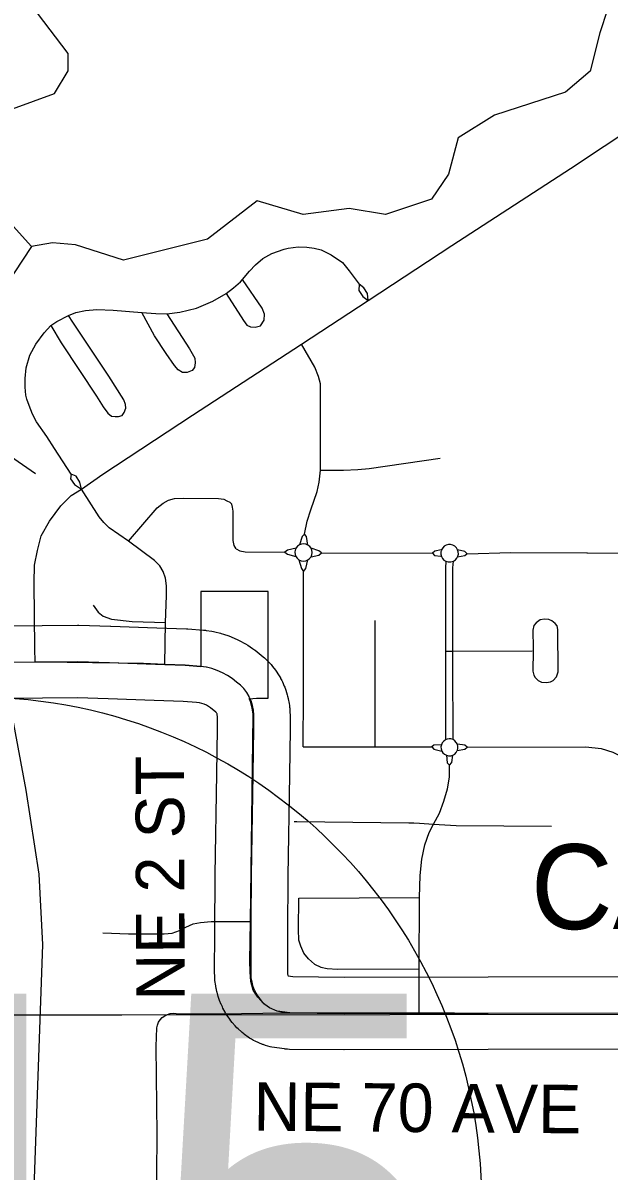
# Model space of a CAD drawing. Extents: x -1403959 to 81668, y -1400582 to 11018.
# Drawn here: x 7193.8 to 7240.5, y 8904.3 to 8995.9 of the extents above; entities that cross this region are included whole.
import ezdxf

# ---------------------------------------------------------------- set-up
doc = ezdxf.new("R2010")
doc.units = 0
for name, color, linetype in [('tdCiCityDivCarto', 7, 'Continuous'), ('tdCiCoBndryTxt', 7, 'Continuous'), ('tdCiRRCL', 7, 'Continuous'), ('tdCiSectLine', 7, 'Continuous'), ('tdCiSectTwpRng', 7, 'Continuous'), ('tdCiUABTitleFrame', 7, 'Continuous'), ('tdCoCityStreetMajor', 7, 'Continuous'), ('tdCoClipBndry', 7, 'Continuous'), ('tdCoDivCarto', 7, 'Continuous'), ('tdCoSectNmbr', 7, 'Continuous'), ('tdCoStrucSecCoName', 7, 'Continuous'), ('tdCoSurfAsphalt', 7, 'Continuous'), ('tdCoSurfBitum', 7, 'Continuous'), ('tdCoSurfEarth', 7, 'Continuous'), ('tdCoTwpNameTxt', 7, 'Continuous')]:
    doc.layers.add(name, color=color, linetype=linetype)

msp = doc.modelspace()

# ---------------------------------------------------------------- linework, layer by layer
at = {"layer": 'tdCiCityDivCarto'}
msp.add_lwpolyline([(7204.662, 8895.454), (7204.534, 8895.98), (7204.469, 8896.616), (7204.417, 8898.277), (7204.456, 8900.703), (7204.43, 8903.623), (7204.434, 8904.02), (7204.461, 8907.198), (7204.397, 8914.226), (7204.429, 8915.705), (7204.487, 8915.937), (7204.583, 8916.155), (7204.715, 8916.354), (7204.88, 8916.527), (7205.071, 8916.67), (7205.284, 8916.778), (7205.512, 8916.847), (7205.749, 8916.877), (7205.987, 8916.866), (7209.502, 8916.835), (7214.602, 8916.899), (7215.067, 8916.898)], dxfattribs=at)
at = {"layer": 'tdCiCoBndryTxt'}
for points in [[(7190.264, 8944.892), (7192.488, 8944.899), (7194.719, 8944.916), (7198.135, 8944.942), (7200.657, 8944.875), (7204.341, 8944.743), (7205.09, 8944.716), (7206.698, 8944.66), (7207.943, 8944.56)], [(7211.852, 8942.059), (7211.81, 8942.152), (7211.614, 8942.481), (7211.38, 8942.785), (7211.112, 8943.059), (7210.814, 8943.299), (7210.459, 8943.585), (7210.081, 8943.838), (7209.683, 8944.057), (7209.266, 8944.24), (7208.835, 8944.386), (7208.411, 8944.488), (7208.393, 8944.493), (7207.943, 8944.56)], [(7211.887, 8941.98), (7211.852, 8942.059)], [(7211.981, 8924.194), (7212.008, 8927.865), (7212.141, 8935.964), (7212.191, 8939.565), (7212.174, 8940.677), (7212.15, 8941.059), (7212.08, 8941.436), (7211.967, 8941.802), (7211.887, 8941.98)], [(7215.067, 8916.898), (7214.047, 8917.053), (7213.447, 8917.315), (7213.156, 8917.53), (7212.89, 8917.775), (7212.652, 8918.048), (7212.446, 8918.346), (7212.274, 8918.664), (7212.138, 8918.999), (7212.039, 8919.347), (7211.979, 8919.704), (7211.959, 8920.066), (7211.975, 8923.368), (7211.981, 8924.194)], [(7215.067, 8916.898), (7219.393, 8916.866), (7225.382, 8916.875), (7230.891, 8916.882), (7241.8, 8916.914), (7244.726, 8916.898), (7251.584, 8916.861)]]:
    msp.add_lwpolyline(points, dxfattribs=at)
at = {"layer": 'tdCiRRCL'}
msp.add_lwpolyline([(7251.584, 8916.859), (7228.211, 8916.885), (7225.36, 8916.875), (7214.602, 8916.899), (7214.047, 8917.053), (7213.447, 8917.315), (7212.985, 8917.623), (7212.508, 8918.162), (7212.123, 8918.732), (7211.938, 8919.425), (7211.892, 8920.149), (7211.877, 8921.058), (7211.924, 8924.194), (7212.141, 8940.627), (7212.122, 8940.771), (7212.064, 8941.213), (7211.925, 8941.767), (7211.823, 8941.973), (7212.394, 8942.036), (7213.334, 8942.036), (7213.334, 8950.54), (7207.952, 8950.54), (7207.952, 8944.678), (7207.943, 8944.56), (7206.698, 8944.66), (7205.043, 8944.718), (7203.388, 8944.777), (7197.286, 8944.864), (7192.488, 8944.899)], dxfattribs=at)
at = {"layer": 'tdCiSectLine'}
for points in [[(7192.472, 8947.801), (7198.113, 8947.844), (7198.135, 8947.844), (7198.211, 8947.843), (7200.734, 8947.776), (7200.762, 8947.775), (7204.445, 8947.643), (7206.8, 8947.56), (7206.888, 8947.555), (7206.929, 8947.552), (7208.174, 8947.453), (7208.321, 8947.437), (7208.374, 8947.43), (7208.824, 8947.362), (7208.959, 8947.339), (7209.075, 8947.313), (7209.517, 8947.206), (7209.586, 8947.189), (7209.763, 8947.135), (7210.194, 8946.989), (7210.199, 8946.988), (7210.377, 8946.921), (7210.433, 8946.897), (7210.85, 8946.714), (7210.966, 8946.66), (7211.079, 8946.601), (7211.478, 8946.381), (7211.532, 8946.351), (7211.694, 8946.251), (7211.697, 8946.248), (7212.075, 8945.995), (7212.226, 8945.887), (7212.28, 8945.844), (7212.933, 8945.318), (7213.025, 8945.24), (7213.164, 8945.111), (7213.186, 8945.089), (7213.454, 8944.815), (7213.562, 8944.698), (7213.679, 8944.556), (7213.913, 8944.252), (7213.916, 8944.248), (7214.027, 8944.093), (7214.106, 8943.968), (7214.302, 8943.639), (7214.323, 8943.603), (7214.413, 8943.436), (7214.461, 8943.334), (7214.617, 8942.984), (7214.647, 8942.913), (7214.714, 8942.735), (7214.738, 8942.663), (7214.851, 8942.297), (7214.883, 8942.187), (7214.926, 8942.002), (7214.934, 8941.963), (7215.003, 8941.587), (7215.027, 8941.438), (7215.045, 8941.249), (7215.046, 8941.246), (7215.07, 8940.863), (7215.076, 8940.72), (7215.093, 8939.608), (7215.093, 8939.565), (7215.093, 8939.525), (7215.043, 8935.924), (7215.043, 8935.916), (7214.91, 8927.831), (7214.877, 8923.35), (7214.861, 8920.141), (7214.867, 8920.028), (7214.874, 8919.986), (7214.886, 8919.944), (7214.902, 8919.905), (7214.923, 8919.867), (7214.932, 8919.854), (7215.296, 8919.799), (7219.402, 8919.768), (7230.884, 8919.784), (7241.791, 8919.816)], [(7241.796, 8914.012), (7230.899, 8913.98), (7230.895, 8913.98), (7219.397, 8913.964), (7219.393, 8913.964), (7219.372, 8913.965), (7215.045, 8913.997), (7214.877, 8914.003), (7214.688, 8914.021), (7214.631, 8914.029), (7213.612, 8914.184), (7213.481, 8914.207), (7213.296, 8914.25), (7213.115, 8914.305), (7212.937, 8914.372), (7212.887, 8914.393), (7212.287, 8914.655), (7212.164, 8914.712), (7211.996, 8914.802), (7211.835, 8914.902), (7211.724, 8914.98), (7211.433, 8915.195), (7211.389, 8915.227), (7211.242, 8915.348), (7211.188, 8915.397), (7210.922, 8915.643), (7210.838, 8915.723), (7210.708, 8915.862), (7210.7, 8915.871), (7210.462, 8916.145), (7210.35, 8916.282), (7210.267, 8916.396), (7210.061, 8916.693), (7210.034, 8916.734), (7209.933, 8916.895), (7209.894, 8916.965), (7209.722, 8917.283), (7209.672, 8917.381), (7209.593, 8917.554), (7209.586, 8917.571), (7209.45, 8917.906), (7209.39, 8918.066), (7209.346, 8918.208), (7209.247, 8918.556), (7209.236, 8918.596), (7209.193, 8918.781), (7209.177, 8918.866), (7209.117, 8919.223), (7209.102, 8919.326), (7209.084, 8919.515), (7209.082, 8919.54), (7209.062, 8919.901), (7209.057, 8920.066), (7209.057, 8920.08), (7209.073, 8923.383), (7209.074, 8923.389), (7209.107, 8927.887), (7209.107, 8927.913), (7209.24, 8936.008), (7209.289, 8939.563), (7209.274, 8940.562), (7209.265, 8940.701), (7209.258, 8940.74), (7209.246, 8940.777), (7209.23, 8940.813), (7209.21, 8940.847), (7209.186, 8940.878), (7209.158, 8940.906), (7208.738, 8941.245), (7208.572, 8941.356), (7208.398, 8941.452), (7208.216, 8941.532), (7208.028, 8941.595), (7207.835, 8941.642), (7207.611, 8941.676), (7206.531, 8941.762), (7204.239, 8941.843), (7204.237, 8941.843), (7200.567, 8941.975), (7198.108, 8942.04), (7192.51, 8941.998)]]:
    msp.add_lwpolyline(points, dxfattribs=at)
at = {"layer": 'tdCiSectTwpRng'}
for points in [[(7238.912, 8985.249), (7251.647, 8993.648), (7255.058, 8995.875)], [(7194.689, 8952.648), (7194.689, 8952.65), (7194.905, 8953.807), (7195.219, 8954.983), (7195.866, 8956.16), (7196.787, 8957.375), (7197.611, 8958.199), (7198.415, 8958.713), (7200.12, 8959.904), (7207.277, 8964.61), (7215.983, 8970.278), (7221.313, 8973.767), (7228.001, 8978.139), (7238, 8984.648), (7238.912, 8985.249)], [(7197.592, 8959.91), (7196.282, 8961.949), (7195.647, 8962.91), (7194.843, 8964.082), (7194.517, 8964.69), (7194.24, 8965.391), (7194.072, 8965.896), (7193.996, 8966.205), (7193.925, 8966.835), (7193.925, 8967.546), (7194.023, 8968.399), (7194.311, 8969.398), (7194.772, 8970.266), (7195.435, 8971.189), (7195.982, 8971.762), (7196.461, 8972.096), (7197.391, 8972.556), (7197.981, 8972.791), (7198.747, 8972.965), (7199.648, 8973.041), (7200.956, 8972.992), (7203.249, 8972.793), (7204.355, 8972.731), (7205.244, 8972.706), (7206.277, 8972.824), (7207.597, 8973.16), (7208.9, 8973.698), (7209.964, 8974.319), (7210.556, 8974.762), (7211.126, 8975.251), (7211.286, 8975.443), (7211.837, 8976.092), (7212.331, 8976.619), (7212.912, 8977.118), (7213.629, 8977.498), (7214.606, 8977.862), (7214.915, 8977.949), (7215.735, 8978.036), (7216.414, 8978.025), (7217, 8977.938), (7217.549, 8977.792), (7218.358, 8977.401), (7219.275, 8976.787), (7219.807, 8976.136), (7220.586, 8975.073)], [(7209.964, 8974.319), (7211.351, 8972.157), (7211.613, 8971.799), (7211.923, 8971.656), (7212.281, 8971.632), (7212.71, 8971.751), (7213.021, 8972.181), (7213.044, 8972.658), (7212.854, 8973.135), (7211.286, 8975.443)], [(7220.586, 8975.073), (7220.57, 8974.563), (7220.893, 8974.077), (7221.313, 8973.767)], [(7221.313, 8973.767), (7221.265, 8974.31), (7220.969, 8974.783), (7220.586, 8975.073)], [(7205.244, 8972.706), (7207.057, 8969.915), (7207.463, 8969.151), (7207.51, 8968.794), (7207.439, 8968.412), (7207.272, 8968.173), (7206.866, 8968.006), (7206.485, 8968.006), (7206.151, 8968.221), (7205.864, 8968.579), (7205.197, 8969.533), (7204.266, 8970.94), (7203.249, 8972.793)], [(7195.982, 8971.762), (7196.8, 8970.392), (7198.255, 8968.173), (7199.615, 8966.122), (7200.163, 8965.263), (7200.521, 8964.762), (7200.831, 8964.524), (7201.118, 8964.5), (7201.38, 8964.5), (7201.666, 8964.595), (7201.833, 8964.81), (7201.976, 8965.168), (7201.952, 8965.454), (7201.809, 8965.836), (7200.617, 8967.72), (7197.73, 8972.038), (7197.391, 8972.556)], [(7216.237, 8955.106), (7216.434, 8956.14), (7216.723, 8957.047), (7217.244, 8958.514), (7217.399, 8959.266), (7217.495, 8960.231), (7217.515, 8965.75), (7217.495, 8967.12), (7217.36, 8967.699), (7217.051, 8968.452), (7215.983, 8970.278)], [(7217.495, 8960.231), (7219.333, 8960.207), (7220.496, 8960.283), (7221.391, 8960.35), (7227.066, 8961.165)], [(7197.592, 8959.91), (7197.562, 8959.523), (7197.877, 8959.063), (7198.415, 8958.713)], [(7198.415, 8958.713), (7198.3, 8959.262), (7198.01, 8959.729), (7197.592, 8959.91)], [(7205.09, 8944.716), (7205.127, 8948.052), (7205.207, 8950.216), (7205.215, 8950.986), (7205.127, 8951.596), (7204.946, 8952.126), (7204.684, 8952.576), (7204.263, 8952.998), (7202.179, 8954.552), (7200.632, 8955.627), (7200.218, 8956.048), (7199.84, 8956.484), (7198.415, 8958.713)], [(7202.179, 8954.552), (7204.47, 8957.204), (7204.941, 8957.595), (7205.382, 8957.82), (7205.842, 8957.948), (7206.596, 8957.987), (7209.376, 8957.948), (7209.786, 8957.905), (7210.04, 8957.785), (7210.263, 8957.654)], [(7210.782, 8953.945), (7210.623, 8954.212), (7210.531, 8954.601), (7210.536, 8956.956), (7210.494, 8957.273), (7210.426, 8957.499), (7210.263, 8957.654)], [(7216.237, 8955.106), (7216.045, 8954.918), (7215.824, 8954.25)], [(7216.503, 8954.238), (7216.392, 8954.914), (7216.237, 8955.106)], [(7210.782, 8953.945), (7211.062, 8953.777), (7211.488, 8953.69), (7214.651, 8953.667)], [(7215.562, 8954.006), (7214.869, 8953.826), (7214.651, 8953.667)], [(7214.651, 8953.667), (7214.861, 8953.504), (7215.545, 8953.329)], [(7215.564, 8953.997), (7215.496, 8953.846), (7215.467, 8953.671), (7215.484, 8953.495), (7215.545, 8953.329)], [(7215.569, 8954.008), (7215.562, 8954.006)], [(7216.749, 8953.987), (7216.643, 8954.129), (7216.503, 8954.238), (7216.34, 8954.308), (7216.165, 8954.334), (7215.989, 8954.314), (7215.824, 8954.25), (7215.681, 8954.145), (7215.569, 8954.008)], [(7217.593, 8953.634), (7217.379, 8953.793), (7216.749, 8953.987)], [(7216.749, 8953.308), (7216.816, 8953.472), (7216.839, 8953.647), (7216.817, 8953.823), (7216.749, 8953.987)], [(7216.749, 8953.308), (7217.383, 8953.445), (7217.593, 8953.634)], [(7217.593, 8953.634), (7226.435, 8953.589)], [(7227.147, 8953.858), (7226.628, 8953.756), (7226.435, 8953.589)], [(7226.435, 8953.589), (7226.615, 8953.404), (7227.11, 8953.343)], [(7227.156, 8953.814), (7227.12, 8953.691), (7227.115, 8953.511), (7227.156, 8953.337), (7227.239, 8953.178), (7227.36, 8953.046), (7227.51, 8952.948)], [(7227.17, 8953.863), (7227.147, 8953.858)], [(7228.453, 8953.871), (7228.359, 8954.024), (7228.229, 8954.147), (7228.072, 8954.234), (7227.898, 8954.278), (7227.719, 8954.277), (7227.546, 8954.231), (7227.391, 8954.142), (7227.262, 8954.016), (7227.17, 8953.863)], [(7228.125, 8952.953), (7228.274, 8953.052), (7228.394, 8953.186), (7228.454, 8953.305), (7228.475, 8953.346), (7228.513, 8953.521), (7228.505, 8953.7), (7228.453, 8953.871)], [(7229.185, 8953.574), (7229.025, 8953.727), (7228.453, 8953.871)], [(7228.454, 8953.305), (7229.025, 8953.409), (7229.202, 8953.553)], [(7229.202, 8953.553), (7229.205, 8953.555)], [(7229.205, 8953.555), (7232.708, 8953.642), (7238.777, 8953.623), (7238.811, 8953.623)], [(7238.811, 8953.623), (7241.557, 8953.585), (7244.506, 8953.642)], [(7194.719, 8944.916), (7194.709, 8945.984), (7194.65, 8951.238), (7194.689, 8952.648)], [(7215.545, 8953.329), (7215.647, 8953.184), (7215.783, 8953.07), (7215.967, 8952.982), (7216.133, 8952.957), (7216.331, 8952.982), (7216.503, 8953.057), (7216.642, 8953.166), (7216.749, 8953.308)], [(7215.783, 8953.07), (7215.986, 8952.366), (7216.153, 8952.132)], [(7216.153, 8952.132), (7216.329, 8952.366), (7216.503, 8953.057)], [(7227.11, 8953.343), (7227.156, 8953.337)], [(7227.51, 8952.948), (7227.49, 8952.4), (7227.49, 8945.787), (7227.49, 8944.776), (7227.49, 8939.288), (7227.483, 8938.696)], [(7227.51, 8952.948), (7227.711, 8952.898), (7227.908, 8952.894), (7228.125, 8952.953)], [(7228.086, 8938.713), (7228.081, 8944.787), (7228.081, 8945.787), (7228.081, 8952.422), (7228.125, 8952.953)], [(7216.131, 8938.138), (7216.142, 8942.333), (7216.153, 8948.73), (7216.153, 8952.132)], [(7199.354, 8949.446), (7199.768, 8948.887), (7200.167, 8948.56), (7200.814, 8948.328), (7202.462, 8948.154), (7205.127, 8948.052)], [(7221.871, 8948.167), (7221.871, 8948.226)], [(7221.871, 8938.149), (7221.871, 8948.167)], [(7234.475, 8945.801), (7234.461, 8944.178), (7234.544, 8943.859), (7234.655, 8943.664), (7234.877, 8943.428), (7235.155, 8943.29), (7235.557, 8943.262), (7235.862, 8943.317), (7236.07, 8943.442), (7236.334, 8943.72), (7236.487, 8944.122), (7236.445, 8947.507), (7236.39, 8947.799), (7236.251, 8947.979), (7235.973, 8948.201), (7235.724, 8948.298), (7235.377, 8948.326), (7235.03, 8948.27), (7234.725, 8948.048), (7234.544, 8947.812), (7234.461, 8947.452), (7234.473, 8946.005), (7234.475, 8945.801)], [(7227.49, 8945.787), (7228.081, 8945.787), (7234.403, 8945.801)], [(7228.433, 8938.344), (7228.35, 8938.496), (7228.232, 8938.621), (7228.086, 8938.713), (7227.906, 8938.772), (7227.78, 8938.78), (7227.625, 8938.755), (7227.483, 8938.696), (7227.342, 8938.597), (7227.231, 8938.464), (7227.157, 8938.309)], [(7216.131, 8938.138), (7221.871, 8938.149), (7226.404, 8938.131)], [(7227.157, 8938.309), (7226.554, 8938.278), (7226.404, 8938.131)], [(7226.404, 8938.131), (7226.563, 8937.956), (7227.191, 8937.803)], [(7227.157, 8938.309), (7227.125, 8938.139), (7227.136, 8937.967), (7227.191, 8937.803)], [(7228.427, 8937.838), (7229.04, 8937.943), (7229.217, 8938.121)], [(7229.217, 8938.121), (7229.04, 8938.274), (7228.433, 8938.344)], [(7228.437, 8937.874), (7228.472, 8938.004), (7228.474, 8938.177), (7228.433, 8938.344)], [(7229.217, 8938.121), (7238.685, 8938.127), (7239.912, 8938.012), (7240.85, 8937.703), (7241.8, 8937.241), (7242.481, 8936.714), (7243.226, 8935.879), (7244.048, 8936.521), (7244.717, 8936.971), (7245.192, 8937.228), (7245.719, 8937.421), (7246.816, 8937.728), (7247.561, 8937.784), (7264.117, 8937.835)], [(7227.191, 8937.803), (7227.285, 8937.659), (7227.413, 8937.543), (7227.566, 8937.462), (7227.734, 8937.424), (7227.906, 8937.428), (7228.072, 8937.477), (7228.22, 8937.565), (7228.341, 8937.688), (7228.427, 8937.838)], [(7227.566, 8937.462), (7227.613, 8936.872), (7227.801, 8936.688)], [(7227.801, 8936.688), (7227.989, 8936.885), (7228.072, 8937.477)], [(7225.382, 8916.875), (7225.382, 8920.424), (7225.42, 8926.115), (7225.459, 8927.875), (7225.587, 8929.173), (7225.844, 8930.316), (7226.178, 8931.305), (7226.525, 8931.961), (7227.013, 8932.834), (7227.36, 8933.798), (7227.656, 8934.8), (7227.797, 8935.725), (7227.801, 8936.688)], [(7215.412, 8932.179), (7215.607, 8932.18), (7224.548, 8932.079), (7224.964, 8932.068), (7225.408, 8932.035), (7226.525, 8931.961), (7228.349, 8931.858), (7235.955, 8931.817)], [(7216.543, 8921.22), (7216.183, 8921.683), (7215.926, 8922.222), (7215.785, 8922.711), (7215.759, 8923.559), (7215.771, 8926.065)], [(7215.771, 8926.065), (7225.42, 8926.115)], [(7216.543, 8921.22), (7217.031, 8920.796), (7217.532, 8920.565), (7218.046, 8920.437), (7218.855, 8920.398), (7225.382, 8920.424)]]:
    msp.add_lwpolyline(points, dxfattribs=at)
at = {"layer": 'tdCiUABTitleFrame'}
msp.add_lwpolyline([(7200.129, 8923.301), (7202.186, 8923.223), (7205.027, 8923.208), (7205.674, 8923.269), (7206.243, 8923.47), (7206.767, 8923.747), (7207.352, 8924.024), (7207.921, 8924.132), (7208.784, 8924.194), (7211.924, 8924.194), (7211.981, 8924.194)], dxfattribs=at)
at = {"layer": 'tdCoCityStreetMajor'}
msp.add_lwpolyline([(7192.239, 8916.751), (7209.936, 8916.772)], dxfattribs=at)
at = {"layer": 'tdCoClipBndry'}
msp.add_lwpolyline([(6862.335, 8918.125), (6892.057, 8918.18), (6899.466, 8918.207), (6996.246, 8917.313), (7001.547, 8917.299), (7117.198, 8916.986), (7192.239, 8916.751), (7201.649, 8916.762), (7287.199, 8916.862), (7384.127, 8916.677)], dxfattribs=at)
at = {"layer": 'tdCoDivCarto'}
msp.add_lwpolyline([(7190.826, 8799.414), (7192.082, 8832.085), (7192.619, 8848.003), (7193.233, 8863.36), (7195.125, 8916.363), (7195.331, 8922.368), (7195.038, 8927.966), (7194.014, 8934.683), (7188.075, 8966.423), (7186.904, 8973.298), (7186.015, 8981.132), (7185.644, 8986.665), (7185.52, 8996.555), (7185.701, 9012.297), (7202.972, 9011.458), (7227.655, 9011.075), (7278.262, 9010.674), (7284.835, 9010.633), (7284.559, 8988.925), (7284.459, 8960.033)], dxfattribs=at)
at = {"layer": 'tdCoSurfAsphalt'}
msp.add_circle((7190.039, 8901.788), 40.327, dxfattribs=at)
at = {"layer": 'tdCoSurfBitum'}
for points in [[(7192.922, 8989.049), (7196.282, 8990.268), (7197.352, 8992.099), (7197.353, 8993.473), (7194.911, 8996.681), (7194.912, 8998.513), (7196.746, 9001.413), (7196.9, 9003.244), (7195.831, 9005.078), (7196.291, 9007.825), (7196.902, 9009.504), (7196.599, 9012.405), (7195.989, 9014.543), (7196.449, 9018.207), (7197.825, 9020.954), (7197.826, 9021.87), (7193.704, 9024.62)], [(7242.253, 9002.6), (7239.806, 8995.122), (7239.04, 8992.068), (7237.055, 8990.391), (7231.403, 8988.563), (7228.501, 8986.733), (7227.736, 8983.833), (7226.361, 8981.849), (7222.695, 8980.631), (7219.794, 8981.09), (7216.129, 8980.635), (7212.464, 8981.707), (7208.492, 8978.656), (7201.772, 8976.982), (7197.955, 8978.206), (7196.123, 8978.36), (7194.443, 8978.056)], [(7194.443, 8978.056), (7191.238, 8981.57)], [(7194.443, 8978.056), (7191.692, 8973.936)]]:
    msp.add_lwpolyline(points, dxfattribs=at)
at = {"layer": 'tdCoSurfEarth'}
msp.add_line((7190.658, 8962.775), (7194.759, 8959.959), dxfattribs=at)
at = {"layer": 'tdCoTwpNameTxt'}
msp.add_lwpolyline([(7117.198, 8916.986), (7136.3, 8916.926), (7171.495, 8916.816), (7192.239, 8916.751), (7201.649, 8916.762)], dxfattribs=at)

# ---------------------------------------------------------------- texts
at = {"layer": 'tdCoSectNmbr'}
for s, rotation, p in [('NE 2 ST', 90.18242, (7206.671, 8917.89)), ('NE 70 AVE', 359.51191, (7212.149, 8907.51))]:
    msp.add_text(s, height=3.8691, rotation=rotation, dxfattribs=at).set_placement(p)
at = {"layer": 'tdCoStrucSecCoName'}
msp.add_text('CARNEY', height=6.7709, dxfattribs=at).set_placement((7234.295, 8923.594))
msp.add_text('CARNEY', height=6.7709, dxfattribs=at).set_placement((7234.295, 8923.594))
at = {"layer": 'tdCoSurfAsphalt'}
msp.add_text('415', height=32.8875, dxfattribs=at).set_placement((7154.624, 8885.56))

doc.saveas('drawing.dxf')
